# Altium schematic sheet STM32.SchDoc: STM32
size A3; Author: Silvio Navaretti; CompanyName: ARDUINO; DrawnBy: Silvio Navaretti; Engineer: Silvio Navaretti; Organization: ARDUINO; SheetNumber: 12; SheetTotal: 51; RevAuthor: Silvio Navaretti
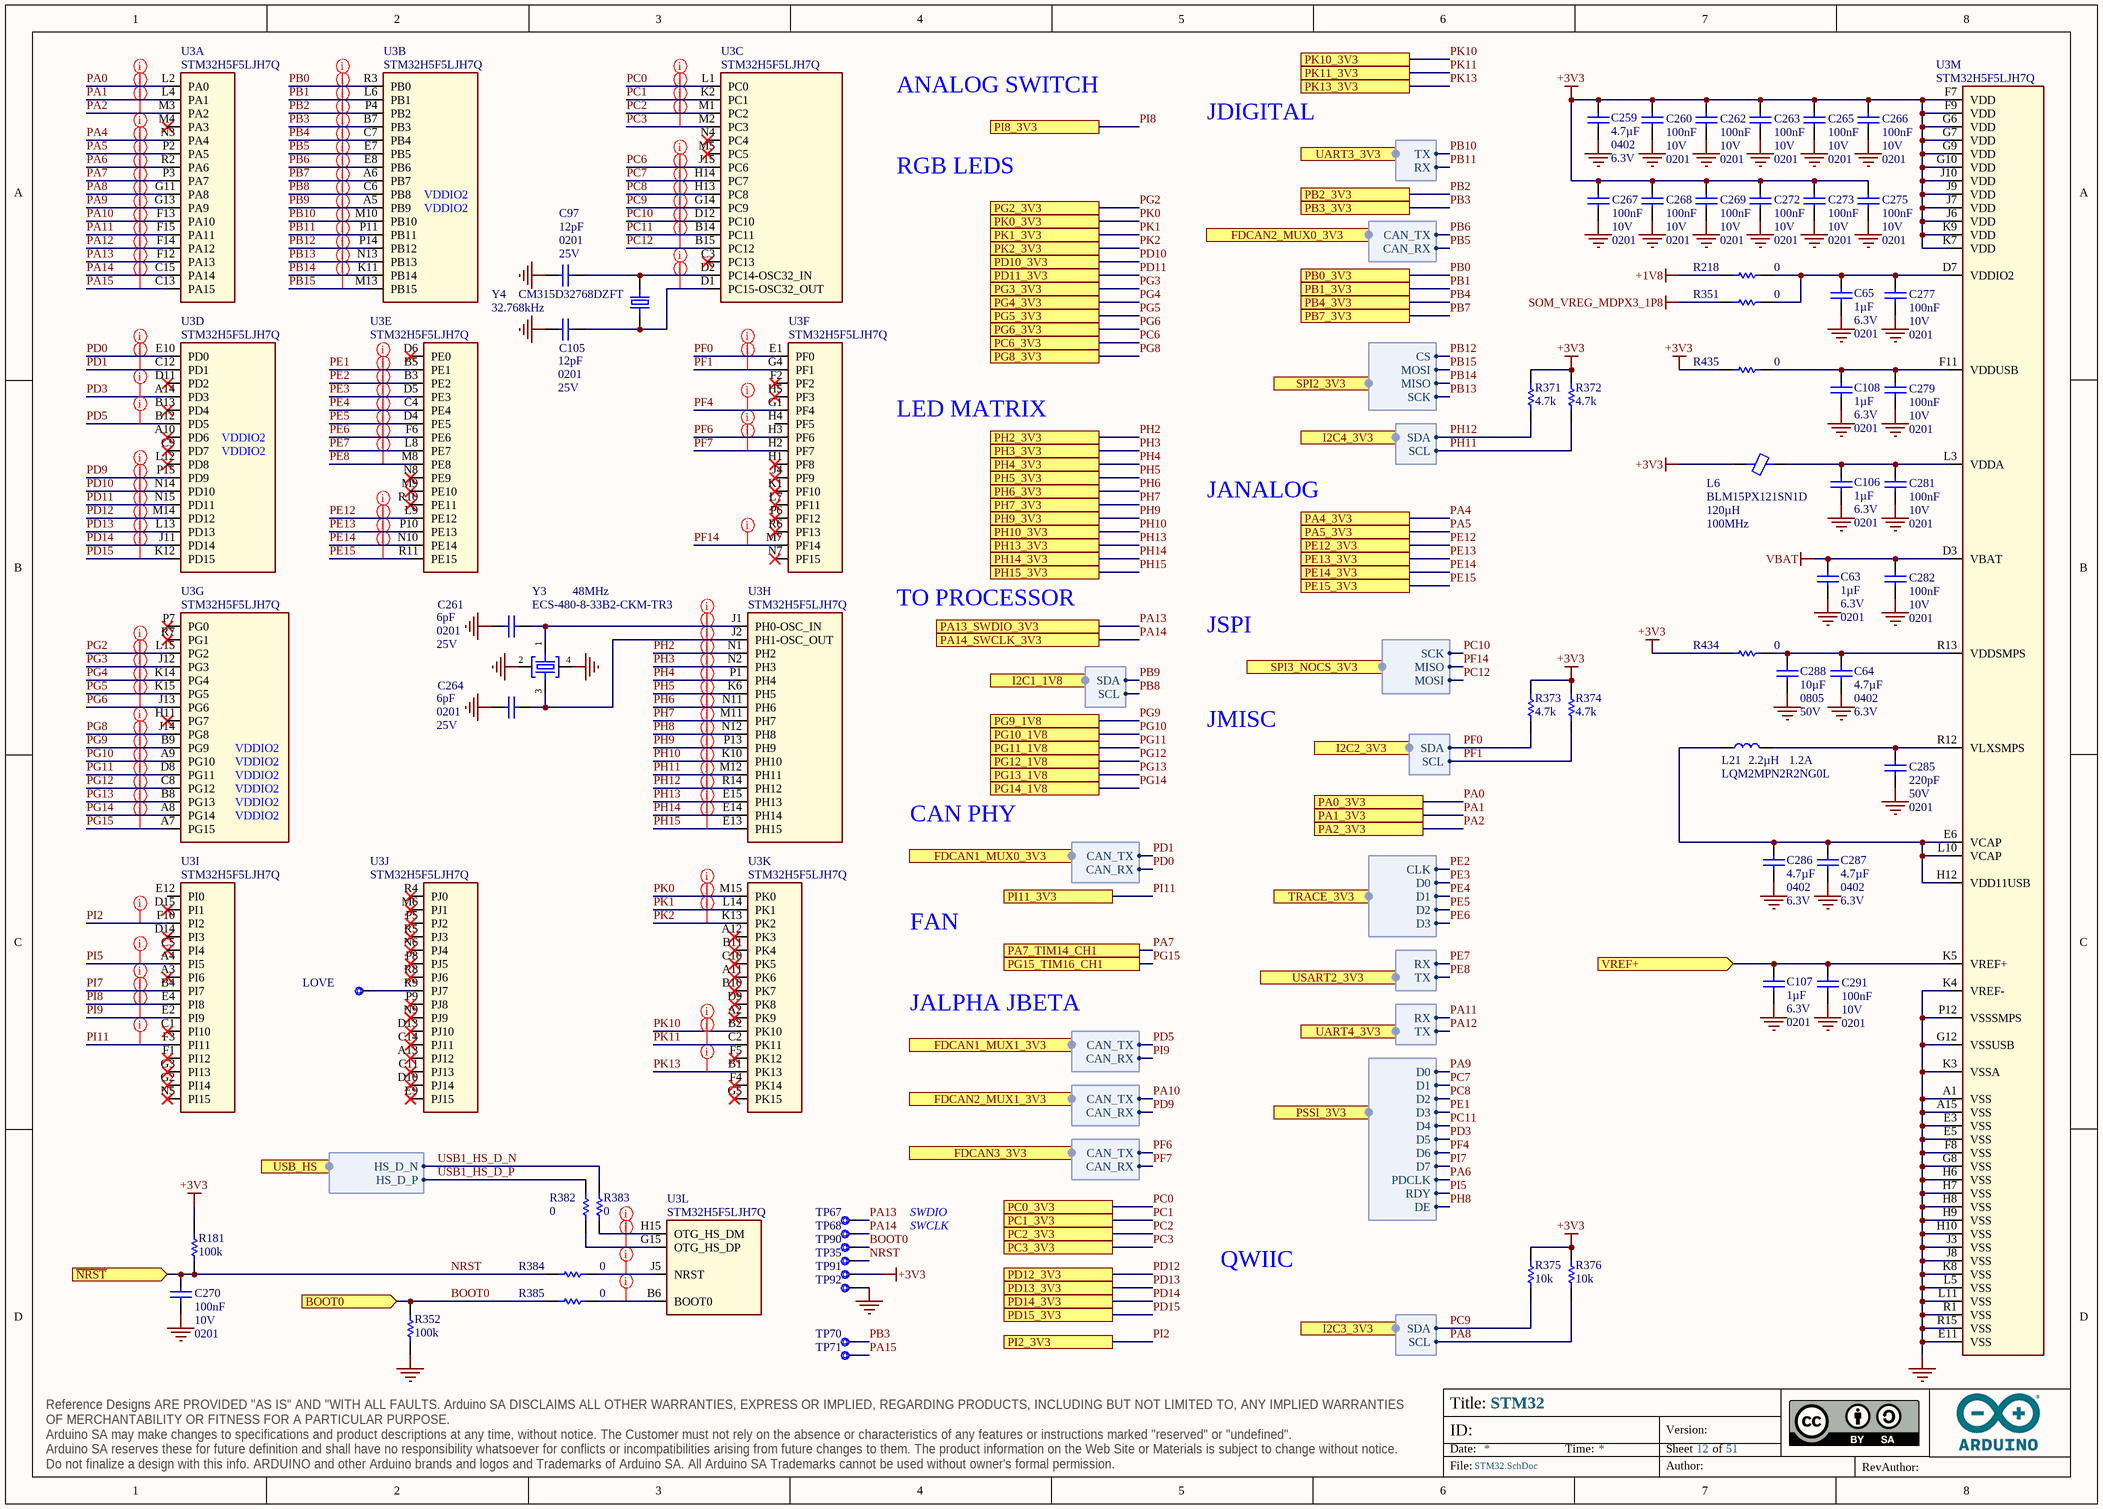
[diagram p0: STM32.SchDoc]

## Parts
C63  value 1µF  Voltage: 6.3V  Case Code (Imperial): 0201  [CAP-0201]  (hidden comment: GRM033R60J105MEA2D)
C64  value 4.7µF  Case Code (Imperial): 0402  Voltage: 6.3V  [CAP-0402]  (hidden comment: C1005A475M6R3NT)
C65  value 1µF  Voltage: 6.3V  Case Code (Imperial): 0201  [CAP-0201]  (hidden comment: GRM033R60J105MEA2D)
C97  value 12pF  Case Code (Imperial): 0201  Voltage: 25V  [CAP-0201]  (hidden comment: GRM0335C1E120JA01J)
C105  value 12pF  Case Code (Imperial): 0201  Voltage: 25V  [CAP-0201]  (hidden comment: GRM0335C1E120JA01J)
C106  value 1µF  Voltage: 6.3V  Case Code (Imperial): 0201  [CAP-0201]  (hidden comment: GRM033R60J105MEA2D)
C107  value 1µF  Voltage: 6.3V  Case Code (Imperial): 0201  [CAP-0201]  (hidden comment: GRM033R60J105MEA2D)
C108  value 1µF  Voltage: 6.3V  Case Code (Imperial): 0201  [CAP-0201]  (hidden comment: GRM033R60J105MEA2D)
C259  value 4.7µF  Case Code (Imperial): 0402  Voltage: 6.3V  [CAP-0402]  (hidden comment: C1005A475M6R3NT)
C260  value 100nF  Voltage: 10V  Case Code (Imperial): 0201  [CAP-0201]  (hidden comment: CL03A104KP3NNNC)
C261  value 6pF  Case Code (Imperial): 0201  Voltage: 25V  [CAP-0201]  (hidden comment: GRM0335C1E6R0CA01D)
C262  value 100nF  Voltage: 10V  Case Code (Imperial): 0201  [CAP-0201]  (hidden comment: CL03A104KP3NNNC)
C263  value 100nF  Voltage: 10V  Case Code (Imperial): 0201  [CAP-0201]  (hidden comment: CL03A104KP3NNNC)
C264  value 6pF  Case Code (Imperial): 0201  Voltage: 25V  [CAP-0201]  (hidden comment: GRM0335C1E6R0CA01D)
C265  value 100nF  Voltage: 10V  Case Code (Imperial): 0201  [CAP-0201]  (hidden comment: CL03A104KP3NNNC)
C266  value 100nF  Voltage: 10V  Case Code (Imperial): 0201  [CAP-0201]  (hidden comment: CL03A104KP3NNNC)
C267  value 100nF  Voltage: 10V  Case Code (Imperial): 0201  [CAP-0201]  (hidden comment: CL03A104KP3NNNC)
C268  value 100nF  Voltage: 10V  Case Code (Imperial): 0201  [CAP-0201]  (hidden comment: CL03A104KP3NNNC)
C269  value 100nF  Voltage: 10V  Case Code (Imperial): 0201  [CAP-0201]  (hidden comment: CL03A104KP3NNNC)
C270  value 100nF  Voltage: 10V  Case Code (Imperial): 0201  [CAP-0201]  (hidden comment: CL03A104KP3NNNC)
C272  value 100nF  Voltage: 10V  Case Code (Imperial): 0201  [CAP-0201]  (hidden comment: CL03A104KP3NNNC)
C273  value 100nF  Voltage: 10V  Case Code (Imperial): 0201  [CAP-0201]  (hidden comment: CL03A104KP3NNNC)
C275  value 100nF  Voltage: 10V  Case Code (Imperial): 0201  [CAP-0201]  (hidden comment: CL03A104KP3NNNC)
C277  value 100nF  Voltage: 10V  Case Code (Imperial): 0201  [CAP-0201]  (hidden comment: CL03A104KP3NNNC)
C279  value 100nF  Voltage: 10V  Case Code (Imperial): 0201  [CAP-0201]  (hidden comment: CL03A104KP3NNNC)
C281  value 100nF  Voltage: 10V  Case Code (Imperial): 0201  [CAP-0201]  (hidden comment: CL03A104KP3NNNC)
C282  value 100nF  Voltage: 10V  Case Code (Imperial): 0201  [CAP-0201]  (hidden comment: CL03A104KP3NNNC)
C285  value 220pF  Voltage: 50V  Case Code (Imperial): 0201  [CAP-0201]  (hidden comment: GRM033R71H221KA12D)
C286  value 4.7µF  Case Code (Imperial): 0402  Voltage: 6.3V  [CAP-0402]  (hidden comment: C1005A475M6R3NT)
C287  value 4.7µF  Case Code (Imperial): 0402  Voltage: 6.3V  [CAP-0402]  (hidden comment: C1005A475M6R3NT)
C288  value 10µF  Case Code (Imperial): 0805  Voltage: 50V  [CAP-0805]  (hidden comment: GRM21BR61H106ME43L)
C291  value 100nF  Voltage: 10V  Case Code (Imperial): 0201  [CAP-0201]  (hidden comment: CL03A104KP3NNNC)
L6  BLM15PX121SN1D  Inductance: 120µH  Test Frequency: 100MHz  [L-0402]
L21  LQM2MPN2R2NG0L  Current: 1.2A  Inductance: 2.2µH  [LQM2MPN2R2NG0L]
LOVE  Test point 1.00mm  [TP-1.00MM]  (value not drawn)  (no BOM)
R181  value 100k  [RES-0201]  (hidden comment: RC0201FR-07100KL)
R218  value 0  [RES-0201]  (hidden comment: CRCW02010000Z0ED)
R351  value 0  [RES-0201]  (hidden comment: CRCW02010000Z0ED)
R352  value 100k  [RES-0201]  (hidden comment: RC0201FR-07100KL)
R371  value 4.7k  [RES-0201]  (hidden comment: RC0201FR-074K7L)
R372  value 4.7k  [RES-0201]  (hidden comment: RC0201FR-074K7L)
R373  value 4.7k  [RES-0201]  (hidden comment: RC0201FR-074K7L)
R374  value 4.7k  [RES-0201]  (hidden comment: RC0201FR-074K7L)
R375  value 10k  [RES-0201]  (hidden comment: RC0201FR-0710KL)
R376  value 10k  [RES-0201]  (hidden comment: RC0201FR-0710KL)
R382  value 0  [RES-0201]  (hidden comment: CRCW02010000Z0ED)
R383  value 0  [RES-0201]  (hidden comment: CRCW02010000Z0ED)
R384  value 0  [RES-0201]  (hidden comment: CRCW02010000Z0ED)
R385  value 0  [RES-0201]  (hidden comment: CRCW02010000Z0ED)
R434  value 0  [RES-0201]  (hidden comment: CRCW02010000Z0ED)
R435  value 0  [RES-0201]  (hidden comment: CRCW02010000Z0ED)
TP35  Test point 1.00mm  [TP-1.00MM]  (value not drawn)  (no BOM)
TP67  Test point 1.00mm  [TP-1.00MM]  (value not drawn)  (no BOM)
TP68  Test point 1.00mm  [TP-1.00MM]  (value not drawn)  (no BOM)
TP70  Test point 1.00mm  [TP-1.00MM]  (value not drawn)  (no BOM)
TP71  Test point 1.00mm  [TP-1.00MM]  (value not drawn)  (no BOM)
TP90  Test point 1.00mm  [TP-1.00MM]  (value not drawn)  (no BOM)
TP91  Test point 1.00mm  [TP-1.00MM]  (value not drawn)  (no BOM)
TP92  Test point 1.00mm  [TP-1.00MM]  (value not drawn)  (no BOM)
U3  STM32H5F5LJH7Q  [BGA225C80P15X15_1300X1300X120]  (parts A,B,C,D,E,F,G,H,I,J,K,L,M of 13)
Y3  ECS-480-8-33B2-CKM-TR3  Frequency: 48MHz  [CRYSTAL3.2X2.5]
Y4  CM315D32768DZFT  Frequency: 32.768kHz  [ABS07]

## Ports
BOOT0 (in), FDCAN1_MUX0_3V3 (harness CAN), FDCAN1_MUX1_3V3 (harness CAN), FDCAN2_MUX0_3V3 (harness CAN), FDCAN2_MUX1_3V3 (harness CAN), FDCAN3_3V3 (harness CAN), I2C1_1V8 (harness I2C), I2C2_3V3 (harness I2C), I2C3_3V3 (harness I2C), I2C4_3V3 (harness I2C), PA0_3V3, PA1_3V3, PA2_3V3, PA4_3V3, PA5_3V3, PA7_TIM14_CH1, PA13_SWDIO_3V3, PA14_SWCLK_3V3, PB0_3V3, PB1_3V3, PB2_3V3, PB3_3V3, PB4_3V3, PB7_3V3, PC0_3V3, PC1_3V3, PC2_3V3, PC3_3V3, PC6_3V3, PD10_3V3, PD11_3V3, PD12_3V3, PD13_3V3, PD14_3V3, PD15_3V3, PE12_3V3, PE13_3V3, PE14_3V3, PE15_3V3, PG2_3V3, PG3_3V3, PG4_3V3, PG5_3V3, PG6_3V3, PG8_3V3, PG9_1V8, PG10_1V8, PG11_1V8, PG12_1V8, PG13_1V8, PG14_1V8, PG15_TIM16_CH1, PH2_3V3, PH3_3V3, PH4_3V3, PH5_3V3, PH6_3V3, PH7_3V3, PH9_3V3, PH10_3V3, PH13_3V3, PH14_3V3, PH15_3V3, PI2_3V3, PI8_3V3, PI11_3V3, PK0_3V3, PK1_3V3, PK2_3V3, PK10_3V3, PK11_3V3, PK13_3V3, PSSI_3V3 (harness PSSI), SPI2_3V3 (harness SPI), SPI3_NOCS_3V3 (harness JSPI_SPI), TRACE_3V3 (harness MCU_TRACE), UART3_3V3 (harness UART), UART4_3V3 (harness UART), USART2_3V3 (harness UART), USB_HS (harness SOM_MD_USB1), VREF+ (in), ~{NRST} (in)

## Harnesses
SPI: SCK, MISO, MOSI, CS
UART: TX, RX
I2C: SDA, SCL
CAN: CAN_TX, CAN_RX
PSSI: D0, D1, D2, D3, D4, D5, D6, D7, PDCLK, RDY, DE
JSPI_SPI: SCK, MISO, MOSI
MCU_TRACE: CLK, D0, D1, D2, D3
SOM_MD_USB1: HS_D_P, HS_D_N

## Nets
+1V8: R218.1
+3V3: C259.1 C260.2 C262.2 C263.2 C265.2 C266.2 C267.2 C268.2 C269.2 C272.2 C273.2 C275.2 L6.1 R181.2 R371.2 R372.2 R373.2 R374.2 R375.2 R376.2 R434.1 R435.1 TP91.X U3.F7(VDD) U3.F9(VDD) U3.G6(VDD) U3.G7(VDD) U3.G9(VDD) U3.G10(VDD) U3.J6(VDD) U3.J7(VDD) U3.J9(VDD) U3.J10(VDD) U3.K7(VDD) U3.K9(VDD)
GND: C63.1 C64.2 C65.1 C97.2 C105.2 C106.1 C107.1 C108.1 C259.2 C260.1 C261.2 C262.1 C263.1 C264.2 C265.1 C266.1 C267.1 C268.1 C269.1 C270.1 C272.1 C273.1 C275.1 C277.1 C279.1 C281.1 C282.1 C285.1 C286.2 C287.2 C288.2 C291.1 R352.1 TP92.X U3.A1(VSS) U3.A15(VSS) U3.E3(VSS) U3.E5(VSS) U3.E11(VSS) U3.F8(VSS) U3.G8(VSS) U3.G12(VSSUSB) U3.H6(VSS) U3.H7(VSS) U3.H8(VSS) U3.H9(VSS) U3.H10(VSS) U3.J3(VSS) U3.J8(VSS) U3.K3(VSSA) U3.K4(VREF-) U3.K8(VSS) U3.L5(VSS) U3.L11(VSS) U3.P12(VSSSMPS) U3.R1(VSS) U3.R15(VSS) Y3.2 Y3.4
SOM_VREG_MDPX3_1P8: R351.1
VBAT: C63.2 C282.2 U3.D3(VBAT)
BOOT0: R352.2 R385.1 TP90.X ; port BOOT0
NRST: C270.2 R181.1 R384.1 TP35.X ; port ~{NRST}
PA0: U3.L2(PA0) ; port PA0_3V3
PA1: U3.L4(PA1) ; port PA1_3V3
PA2: U3.M3(PA2) ; port PA2_3V3
PA4: U3.N3(PA4) ; port PA4_3V3
PA5: U3.P2(PA5) ; port PA5_3V3
PA6: U3.R2(PA6) ; port PSSI_3V3.PDCLK
PA7: U3.P3(PA7) ; port PA7_TIM14_CH1
PA8: R376.1 U3.G11(PA8) ; port I2C3_3V3.SCL
PA9: U3.G13(PA9) ; port PSSI_3V3.D0
PA10: U3.F13(PA10) ; port FDCAN2_MUX1_3V3.CAN_TX
PA11: U3.F15(PA11) ; port UART4_3V3.RX
PA12: U3.F14(PA12) ; port UART4_3V3.TX
PA13: TP67.X U3.F12(PA13) ; port PA13_SWDIO_3V3
PA14: TP68.X U3.C15(PA14) ; port PA14_SWCLK_3V3
PA15: TP71.X U3.C13(PA15)
PB0: U3.R3(PB0) ; port PB0_3V3
PB1: U3.L6(PB1) ; port PB1_3V3
PB2: U3.P4(PB2) ; port PB2_3V3
PB3: TP70.X U3.B7(PB3) ; port PB3_3V3
PB4: U3.C7(PB4) ; port PB4_3V3
PB5: U3.E7(PB5) ; port FDCAN2_MUX0_3V3.CAN_RX
PB6: U3.E8(PB6) ; port FDCAN2_MUX0_3V3.CAN_TX
PB7: U3.A6(PB7) ; port PB7_3V3
PB8: U3.C6(PB8) ; port I2C1_1V8.SCL
PB9: U3.A5(PB9) ; port I2C1_1V8.SDA
PB10: U3.M10(PB10) ; port UART3_3V3.TX
PB11: U3.P11(PB11) ; port UART3_3V3.RX
PB12: U3.P14(PB12) ; port SPI2_3V3.CS
PB13: U3.N13(PB13) ; port SPI2_3V3.SCK
PB14: U3.K11(PB14) ; port SPI2_3V3.MISO
PB15: U3.M13(PB15) ; port SPI2_3V3.MOSI
PC0: U3.L1(PC0) ; port PC0_3V3
PC1: U3.K2(PC1) ; port PC1_3V3
PC2: U3.M1(PC2) ; port PC2_3V3
PC3: U3.M2(PC3) ; port PC3_3V3
PC6: U3.J15(PC6) ; port PC6_3V3
PC7: U3.H14(PC7) ; port PSSI_3V3.D1
PC8: U3.H13(PC8) ; port PSSI_3V3.D2
PC9: R375.1 U3.G14(PC9) ; port I2C3_3V3.SDA
PC10: U3.D12(PC10) ; port SPI3_NOCS_3V3.SCK
PC11: U3.B14(PC11) ; port PSSI_3V3.D4
PC12: U3.B15(PC12) ; port SPI3_NOCS_3V3.MOSI
PD0: U3.E10(PD0) ; port FDCAN1_MUX0_3V3.CAN_RX
PD1: U3.C12(PD1) ; port FDCAN1_MUX0_3V3.CAN_TX
PD3: U3.A14(PD3) ; port PSSI_3V3.D5
PD5: U3.B12(PD5) ; port FDCAN1_MUX1_3V3.CAN_TX
PD9: U3.P15(PD9) ; port FDCAN2_MUX1_3V3.CAN_RX
PD10: U3.N14(PD10) ; port PD10_3V3
PD11: U3.N15(PD11) ; port PD11_3V3
PD12: U3.M14(PD12) ; port PD12_3V3
PD13: U3.L13(PD13) ; port PD13_3V3
PD14: U3.J11(PD14) ; port PD14_3V3
PD15: U3.K12(PD15) ; port PD15_3V3
PE1: U3.B5(PE1) ; port PSSI_3V3.D3
PE2: U3.B3(PE2) ; port TRACE_3V3.CLK
PE3: U3.D5(PE3) ; port TRACE_3V3.D0
PE4: U3.C4(PE4) ; port TRACE_3V3.D1
PE5: U3.D4(PE5) ; port TRACE_3V3.D2
PE6: U3.F6(PE6) ; port TRACE_3V3.D3
PE7: U3.L8(PE7) ; port USART2_3V3.RX
PE8: U3.M8(PE8) ; port USART2_3V3.TX
PE12: U3.L9(PE12) ; port PE12_3V3
PE13: U3.P10(PE13) ; port PE13_3V3
PE14: U3.N10(PE14) ; port PE14_3V3
PE15: U3.R11(PE15) ; port PE15_3V3
PF0: R373.1 U3.E1(PF0) ; port I2C2_3V3.SDA
PF1: R374.1 U3.G4(PF1) ; port I2C2_3V3.SCL
PF4: U3.G1(PF4) ; port PSSI_3V3.D6
PF6: U3.H3(PF6) ; port FDCAN3_3V3.CAN_TX
PF7: U3.H2(PF7) ; port FDCAN3_3V3.CAN_RX
PF14: U3.M7(PF14) ; port SPI3_NOCS_3V3.MISO
PG2: U3.L15(PG2) ; port PG2_3V3
PG3: U3.J12(PG3) ; port PG3_3V3
PG4: U3.K14(PG4) ; port PG4_3V3
PG5: U3.K15(PG5) ; port PG5_3V3
PG6: U3.J13(PG6) ; port PG6_3V3
PG8: U3.J14(PG8) ; port PG8_3V3
PG9: U3.B9(PG9) ; port PG9_1V8
PG10: U3.A9(PG10) ; port PG10_1V8
PG11: U3.D8(PG11) ; port PG11_1V8
PG12: U3.C8(PG12) ; port PG12_1V8
PG13: U3.B8(PG13) ; port PG13_1V8
PG14: U3.A8(PG14) ; port PG14_1V8
PG15: U3.A7(PG15) ; port PG15_TIM16_CH1
PH2: U3.N1(PH2) ; port PH2_3V3
PH3: U3.N2(PH3) ; port PH3_3V3
PH4: U3.P1(PH4) ; port PH4_3V3
PH5: U3.K6(PH5) ; port PH5_3V3
PH6: U3.N11(PH6) ; port PH6_3V3
PH7: U3.M11(PH7) ; port PH7_3V3
PH8: U3.N12(PH8) ; port PSSI_3V3.DE
PH9: U3.P13(PH9) ; port PH9_3V3
PH10: U3.K10(PH10) ; port PH10_3V3
PH11: R372.1 U3.M12(PH11) ; port I2C4_3V3.SCL
PH12: R371.1 U3.R14(PH12) ; port I2C4_3V3.SDA
PH13: U3.E15(PH13) ; port PH13_3V3
PH14: U3.E14(PH14) ; port PH14_3V3
PH15: U3.E13(PH15) ; port PH15_3V3
PI2: U3.F10(PI2) ; port PI2_3V3
PI5: U3.A4(PI5) ; port PSSI_3V3.RDY
PI7: U3.B4(PI7) ; port PSSI_3V3.D7
PI8: U3.E4(PI8) ; port PI8_3V3
PI9: U3.E2(PI9) ; port FDCAN1_MUX1_3V3.CAN_RX
PI11: U3.F3(PI11) ; port PI11_3V3
PK0: U3.M15(PK0) ; port PK0_3V3
PK1: U3.L14(PK1) ; port PK1_3V3
PK2: U3.K13(PK2) ; port PK2_3V3
PK10: U3.B2(PK10) ; port PK10_3V3
PK11: U3.C2(PK11) ; port PK11_3V3
PK13: U3.B1(PK13) ; port PK13_3V3
USB1_HS_D_N: R383.1 ; port USB_HS.HS_D_N
USB1_HS_D_P: R382.1 ; port USB_HS.HS_D_P
VREF+: C107.2 C291.2 U3.K5(VREF+) ; port VREF+
NetC64_1: C64.1 C288.1 R434.2 U3.R13(VDDSMPS)
NetC65_2: C65.2 C277.2 R218.2 R351.2 U3.D7(VDDIO2)
NetC97_1: C97.1 U3.D2(PC14-OSC32_IN) Y4.2
NetC105_1: C105.1 U3.D1(PC15-OSC32_OUT) Y4.1
NetC106_2: C106.2 C281.2 L6.2 U3.L3(VDDA)
NetC108_2: C108.2 C279.2 R435.2 U3.F11(VDDUSB)
NetC261_1: C261.1 U3.J1(PH0-OSC_IN) Y3.1
NetC264_1: C264.1 U3.J2(PH1-OSC_OUT) Y3.3
NetC285_2: C285.2 L21.2 U3.R12(VLXSMPS)
NetC286_1: C286.1 C287.1 L21.1 U3.E6(VCAP) U3.H12(VDD11USB) U3.L10(VCAP)
NetLOVE_X: LOVE.X U3.R9(PJ7)
NetR382_2: R382.2 U3.G15(OTG_HS_DP)
NetR383_2: R383.2 U3.H15(OTG_HS_DM)
NetR384_2: R384.2 U3.J5(NRST)
NetR385_2: R385.2 U3.B6(BOOT0)

Not connected (* = marked no-connect by the designer): U3 A2(PK9)* A3(PI6)* A10(PD6)* A11(PK6)* A12(PK3)* A13(PJ12)* B10(PK7)* B11(PK4)* B13(PD4)* C1(PI10)* C3(PC13)* C5(PI4)* C9(PD7)* C10(PK5)* C11(PJ13)* C14(PJ11)* D6(PE0)* D9(PK8)* D10(PJ14)* D11(PD2)* D13(PJ10)* D14(PI3)* D15(PI1)* E9(PJ15)* E12(PI0) F1(PI12)* F2(PF2)* F4(PK14)* F5(PK12)* G2(PI14)* G3(PI13)* G5(PK15)* H1(PF8)* H4(PF5) H5(PF3)* H11(PG7)* J4(PF9)* K1(PF10)* L7(PF11)* L12(PD8)* M4(PA3)* M5(PC5)* M6(PJ1)* M9(PE10)* N4(PC4)* N5(PI15)* N6(PJ4)* N7(PF15)* N8(PE9)* N9(PJ9)* P5(PJ2)* P6(PF12)* P7(PG0)* P8(PJ5)* P9(PJ8)* R4(PJ0)* R5(PJ3)* R6(PF13)* R7(PG1)* R8(PJ6)* R10(PE11)*

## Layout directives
net class MICROCONTROLLER: NetC97_1, NetC105_1, NetC261_1, NetC264_1, NetR382_2, NetR383_2, NetR384_2, NetR385_2, PA0, PA1, PA2, PA4, PA5, PA6, PA7, PA8, PA9, PA10, PA11, PA12, PA13, PA14, PA15, PB0, PB1, PB2, PB3, PB4, PB5, PB6, PB7, PB8, PB9, PB10, PB11, PB12, PB13, PB14, PB15, PC0, PC1, PC2, PC3, PC6, PC7, PC8, PC9, PC10, PC11, PC12, PD0, PD1, PD3, PD5, PD9, PD10, PD11, PD12, PD13, PD14, PD15, PE1, PE2, PE3, PE4, PE5, PE6, PE7, PE8, PE12, PE13, PE14, PE15, PF0, PF1, PF4, PF6, PF7, PF14, PG2, PG3, PG4, PG5, PG6, PG8, PG9, PG10, PG11, PG12, PG13, PG14, PG15, PH2, PH3, PH4, PH5, PH6, PH7, PH8, PH9, PH10, PH11, PH12, PH13, PH14, PH15, PI2, PI5, PI7, PI8, PI9, PI11, PK0, PK1, PK2, PK10, PK11, PK13

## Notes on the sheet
- ANALOG SWITCH
- RGB LEDS
- JDIGITAL
- LED MATRIX
- JANALOG
- TO PROCESSOR
- JSPI
- JMISC
- CAN PHY
- FAN
- JALPHA JBETA
- SWDIO
- SWCLK
- QWIIC

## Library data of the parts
C63 C65 C106-C108 = C0002-A.15: CAP CHIP 0201 1uF 20% 6.3V X5R; Manufacturer: Murata; Code Arduino: A5520
C64 C259 C286 C287 = C0037-A.14: CAP CHIP 0402 4.7uF 20% 6V3 X5R; Manufacturer: Hottech; Code Arduino: 0833
C97 C105 = C0003-A.15: CAP CHIP 0201 12pF 5% 25V C0G; Manufacturer: Murata; Code Arduino: C0003
C260 C262 C263 C265-C270 C272 C273 C275 C277 C279 C281 C282 C291 = C0113-A.6: CAP CHIP 0201 100nF 10% 10V X5R; Manufacturer: Samsung Electro-Mechanics; Code Arduino: C0113
C261 C264 = C0203-A.1: CAP CHIP 0201 6pF 0.25pF 25V C0G; Manufacturer: Murata; Code Arduino: C0203
C285 = C0202-A.1: CAP CHIP 0201 220pF 10% 50V X7R; Manufacturer: Murata; Code Arduino: C0202
C288 = C0158-A.3: CAP CHIP 0805 10uF 20% 50V X5R; Manufacturer: Murata Electronics; Code Arduino: C0158
L6 = I0028-A.10: FERRITE SMD 0402 120Ohm 25% 100MHz Ferrite 2A; Manufacturer: Murata; DC Resistance (DCR): 55mR; Code Arduino: I0028; Value: 120µH
L21 = I0019-A.10: INDUCTOR SMD 0806 2.2uH 1.2A; Manufacturer: Murata; DC Resistance (DCR): 138mR; Tolerance: 30%; Test Frequency: 1MHz; Code Arduino: A5528
LOVE = UT0013-A.6: Manufacturer: This is not a component
R181 R352 = R0146-A.21: RES CHIP 0201 100k 1% 1/20W; Manufacturer: Yageo; Power: 50mW; Temperature coefficient: 200ppm; Code Arduino: R0146
R218 R351 R382-R385 R434 R435 = R0140-A.21: RES CHIP 0201 0R; Manufacturer: Vishay; Temperature coefficient: 0ppm; Code Arduino: R0140; Power: 50mW; Tolerance: 0%
R371-R374 = R0151-A.21: RES CHIP 0201 4k7 1% 1/20W; Manufacturer: Yageo; Power: 50mW; Temperature coefficient: 200ppm; Code Arduino: A5521
R375 R376 = R0145-A.21: RES CHIP 0201 10k 1% 1/20W; Manufacturer: Yageo; Power: 50mW; Temperature coefficient: 200ppm; Code Arduino: R0145
TP35 TP67 TP68 TP70 TP71 TP90-TP92 = UT0013-A.6: Part Number: This is not a component
U3 = U0520-A.5: IC Cortex M33 250MHz, 4MB flash, 1.5MB RAM, TFBGA225 13x13mm; Manufacturer: ST; Code Arduino: U0520
Y3 = X0035-A.2: CRYSTAL 48MHz tolerance 10ppm stability 15ppm load 10pF, shunt 2pF, ESR 30R, 3.2x2.5mm; Manufacturer: ECS; Load Capacitance: 8pF; ESR (Equivalent Series Resistance): 30; Code Arduino: X0035
Y4 = X0003-A.5: CRYSTAL 32.768kHz 20ppm 12.5pF SMD 1.6x0.9mm; Manufacturer: Citizen FineDevice; Frequency Stability: 0.12%; Code Arduino: 0213; Series Resistance: 70kR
